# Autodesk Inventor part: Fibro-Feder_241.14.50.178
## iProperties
Created: 2001-02
Part Number: Fibro-Feder_241.14.50.178
Material: Steel, Mild
Document SubType Name: Modeling
Description: Druckfeder 40
Density: 7.86 g/cm^3
Mass: 213.938 g
Surface Area: 232.954 cm^2
Volume: 27.2186 cm^3
+MSCProtocol1+ProtocolID: P00061017114949781
+MSCProtocol2+Protocol: P00061017114949781<@PID>[Version]<@EL>Version=2.2<@EL>[Object]<@EL>Description=Komponenten-Generator der Druckfeder<@EL>ProtID=<@EL>Object=TLACNE<@EL>[Synchroni
Control State: 0
Master: False
Checked Out: False
Shininess: 20.0
Length Units: 11269
Angle Units: 11279
Time Units: 11290
Mass Units: 11283
Length Display Precision: 3
Angle Display Precision: 2
TAB_n: 5
TAB_c: 131.1173
TAB_dir: rechts
TAB_F1: 655.59
TAB_F8: 1311.17
TAB_F9: 3867.96
Density: 7.86
Volumn: 4.566057099791777
Area: 34.56163463876042
PropertySet Name: Model Information
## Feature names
1. SweepPathOnly1
2. ExtrusionBlind1
3. ExtrusionBlind2
